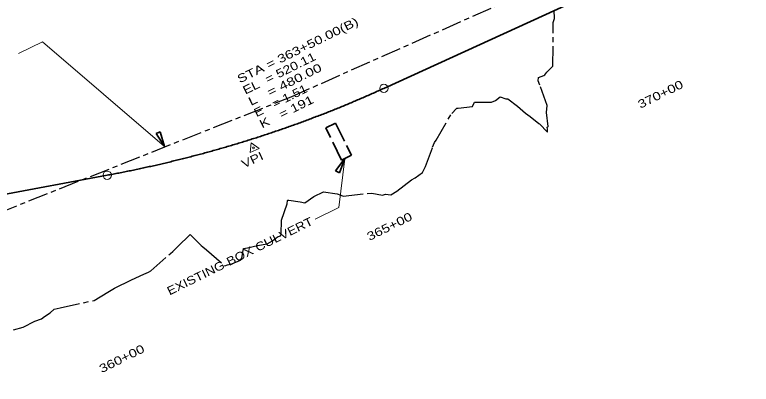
# Model space of a CAD drawing. Extents: x 2356431 to 2371438, y 6972864 to 6982525.
# Drawn here: x 2364327 to 2365561, y 6976258 to 6976877 of the extents above; entities that cross this region are included whole.
import ezdxf
from ezdxf.enums import TextEntityAlignment as Align

# ---------------------------------------------------------------- set-up
doc = ezdxf.new("R2010")
doc.units = 0
doc.header["$LTSCALE"] = 5.6
for name, pattern in [('DASH_DOUBLE_DOT', [9.2, 5, -1.2, 0.3, -1.2, 0.3, -1.2]), ('LONG_DASH_SHORT_DASH', [9.9, 6, -1.2, 1.5, -1.2]), ('LONG_DASHED', [7.5, 6, -1.5])]:
    doc.linetypes.add(name, pattern=pattern)
for name, color, linetype, lineweight in [('1', 7, 'Continuous', 25), ('2', 7, 'Continuous', 35), ('4', 7, 'LONG_DASHED', 35), ('44', 7, 'Continuous', 13), ('52', 7, 'Continuous', 25), ('53', 7, 'Continuous', 13), ('61', 7, 'Continuous', 13)]:
    doc.layers.add(name, color=color, linetype=linetype, lineweight=lineweight)

msp = doc.modelspace()

# ---------------------------------------------------------------- linework, layer by layer
at = {"layer": '1', "linetype": 'LONG_DASH_SHORT_DASH'}
msp.add_line((2363578.139, 6976258.258), (2364790.419, 6976739.461), dxfattribs=at)
for points in [[(2364790.419, 6976739.461), (2365229.723, 6976933.969), (2365545.923, 6977106.752)], [(2365220.149, 6976680.352), (2365220.017, 6976681.882), (2365219.669, 6976684.979), (2365219.309, 6976688.71), (2365220.25, 6976689.175), (2365220.591, 6976689.343), (2365221.057, 6976689.574), (2365218.336, 6976713.315), (2365219.43, 6976724.621), (2365207.133, 6976758.866), (2365204.494, 6976766.261), (2365204.954, 6976771.852), (2365213.589, 6976775.121), (2365215.176, 6976775.905), (2365218.636, 6976780.889), (2365228.954, 6976790.549), (2365229.505, 6976863.956), (2365231.489, 6976870.234), (2365231.213, 6976884.244)], [(2364325.581, 6976349.133), (2364341.661, 6976353.884), (2364361.156, 6976363.821), (2364372.177, 6976367.952), (2364377.12, 6976371.536), (2364387.009, 6976378.001), (2364393.257, 6976383.731), (2364403.234, 6976386.34), (2364460.544, 6976398.578), (2364483.389, 6976412.119), (2364494.335, 6976419.222), (2364522.968, 6976433.06), (2364543.885, 6976442.513), (2364551.433, 6976446.108), (2364555.148, 6976448.251), (2364588.359, 6976477.247), (2364592.118, 6976480.451), (2364599.787, 6976488.225), (2364621.313, 6976509.017), (2364639.87, 6976490.543), (2364642.682, 6976488.328), (2364648.373, 6976483.518), (2364679.599, 6976456.698), (2364683.602, 6976458.122), (2364691.088, 6976459.993), (2364705.575, 6976465.959), (2364707.804, 6976469.393), (2364709.875, 6976481.972), (2364710.46, 6976485.481), (2364717.53, 6976486.726), (2364733.876, 6976490.375), (2364750.194, 6976493.334), (2364759.115, 6976498.079), (2364767.627, 6976505.052), (2364772.643, 6976506.751), (2364773.959, 6976509.551), (2364774.551, 6976532.794), (2364783.66, 6976560.066), (2364784.203, 6976565.717), (2364785.014, 6976566.198), (2364786.745, 6976566.418), (2364805.413, 6976563.788), (2364813.102, 6976561.954), (2364828.201, 6976572.593), (2364844.721, 6976580.086), (2364867.807, 6976576.89), (2364873.865, 6976574.496), (2364877.522, 6976573.302), (2364925.434, 6976578.285), (2364943.351, 6976574.714), (2364948.48, 6976576.435), (2364957.56, 6976575.531), (2364967.451, 6976581.587), (2364991.931, 6976600.509), (2364998.169, 6976604.026), (2365010.252, 6976612.506), (2365015.545, 6976622.492), (2365027.483, 6976654.829), (2365030.45, 6976663.157), (2365033.601, 6976666.96), (2365059.411, 6976711.697), (2365067.662, 6976719.649), (2365068.241, 6976720.215), (2365068.262, 6976720.218), (2365068.283, 6976720.22), (2365068.295, 6976720.218), (2365068.317, 6976720.219), (2365070.204, 6976720.645), (2365094.217, 6976723.358), (2365097.859, 6976730.207), (2365098.042, 6976730.425), (2365098.706, 6976730.436), (2365125.939, 6976730.449), (2365132.973, 6976733.235), (2365140.625, 6976739.058), (2365150.301, 6976735.798), (2365153.682, 6976735.953), (2365169.813, 6976723.764), (2365182.932, 6976712.161), (2365191.106, 6976706.615), (2365202.818, 6976697.135), (2365204.601, 6976695.041), (2365204.862, 6976694.897), (2365205.231, 6976694.737), (2365206.724, 6976694.176), (2365220.149, 6976680.352)]]:
    msp.add_lwpolyline(points, dxfattribs=at)
at = {"layer": '2'}
for p, q in [((2364945.745, 6976753.555), (2365561.252, 6977034.695)), ((2363527.851, 6976429.977), (2364482.273, 6976608.067))]:
    msp.add_line(p, q, dxfattribs=at)
msp.add_spline([(2364482.273, 6976608.067), (2364492.065, 6976609.917), (2364501.836, 6976611.811), (2364511.585, 6976613.749), (2364521.314, 6976615.729), (2364531.02, 6976617.753), (2364540.706, 6976619.82), (2364550.37, 6976621.93), (2364560.012, 6976624.084), (2364569.634, 6976626.28), (2364579.234, 6976628.52), (2364588.812, 6976630.802), (2364598.369, 6976633.128), (2364607.906, 6976635.497), (2364617.42, 6976637.91), (2364626.914, 6976640.366), (2364636.386, 6976642.866), (2364645.837, 6976645.408), (2364655.266, 6976647.993), (2364664.674, 6976650.622), (2364674.061, 6976653.294), (2364683.426, 6976656.009), (2364692.77, 6976658.768), (2364702.093, 6976661.569), (2364711.395, 6976664.414), (2364720.675, 6976667.303), (2364729.934, 6976670.234), (2364739.171, 6976673.208), (2364748.387, 6976676.226), (2364757.582, 6976679.287), (2364766.755, 6976682.392), (2364775.907, 6976685.539), (2364785.038, 6976688.73), (2364794.148, 6976691.963), (2364803.236, 6976695.241), (2364812.303, 6976698.561), (2364821.348, 6976701.925), (2364830.372, 6976705.331), (2364839.375, 6976708.782), (2364848.357, 6976712.275), (2364857.317, 6976715.811), (2364866.256, 6976719.391), (2364875.173, 6976723.014), (2364884.069, 6976726.68), (2364892.944, 6976730.389), (2364901.797, 6976734.142), (2364910.63, 6976737.938), (2364919.44, 6976741.778), (2364928.23, 6976745.659), (2364936.998, 6976749.585), (2364945.744, 6976753.554)], degree=3, dxfattribs=at)
at = {"layer": '4'}
msp.add_lwpolyline([(2364848.333, 6976687.371), (2364864.847, 6976695.521), (2364891.401, 6976641.717), (2364874.886, 6976633.566)], close=True, dxfattribs=at)
at = {"layer": '44'}
for p, q in [((2364870.518, 6976554.13), (2364880.158, 6976636.168)), ((2364830.702, 6976534.479), (2364870.518, 6976554.13))]:
    msp.add_line(p, q, dxfattribs=at)
msp.add_lwpolyline([(2364333.922, 6976811.912), (2364373.738, 6976831.563), (2364578.377, 6976656.476)], dxfattribs=at)
at = {"layer": '53', "linetype": 'DASH_DOUBLE_DOT', "lineweight": 35}
for points in [[(2364570.942, 6976680.96), (2364578.377, 6976656.476), (2364564.089, 6976677.965)], [(2364864.787, 6976615.711), (2364880.158, 6976636.168), (2364871.251, 6976611.948)]]:
    msp.add_lwpolyline(points, close=True, dxfattribs=at)
at = {"layer": '61'}
for p, q in [((2364723.368, 6976662.237), (2364722.035, 6976646.136)), ((2364723.368, 6976662.237), (2364736.649, 6976653.037)), ((2364722.035, 6976646.136), (2364736.649, 6976653.037))]:
    msp.add_line(p, q, dxfattribs=at)
for centre, radius in [((2364945.745, 6976753.555), 7), ((2364727.342, 6976653.796), 1.5), ((2364482.273, 6976608.067), 7)]:
    msp.add_circle(centre, radius, dxfattribs=at)

# ---------------------------------------------------------------- texts
at = {"layer": '44', "width": 1.2}
msp.add_text('EXISTING BOX CULVERT', height=14, rotation=26.268, dxfattribs=at).set_placement((2364707.678, 6976466.556), align=Align.CENTER)
at = {"layer": '52'}
for s, width, p in [('STA = 363+50.00(B)', 1.3, (2364704.448, 6976761.728)), ('EL  = 520.11', 1.25, (2364713.741, 6976742.897)), ('L   = 480.00', 1.35, (2364723.035, 6976724.066)), ('E   = 1.51', 1.2, (2364732.329, 6976705.234)), ('K   = 191', 1.3, (2364741.623, 6976686.403))]:
    msp.add_text(s, height=14, rotation=26.268, dxfattribs=dict(at, width=width)).set_placement(p)
at = {"layer": '53', "width": 1.3}
for s, p in [('370+00', (2365412.211, 6976737.347)), ('365+00', (2364958.225, 6976516.128)), ('360+00', (2364509.788, 6976294.81))]:
    msp.add_text(s, height=14, rotation=26.268, dxfattribs=at).set_placement(p, align=Align.CENTER)
at = {"layer": '61', "width": 1.25}
msp.add_text('VPI', height=14, rotation=25.278, dxfattribs=at).set_placement((2364728.477, 6976627.483), align=Align.CENTER)

doc.saveas('drawing.dxf')
